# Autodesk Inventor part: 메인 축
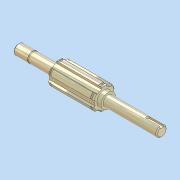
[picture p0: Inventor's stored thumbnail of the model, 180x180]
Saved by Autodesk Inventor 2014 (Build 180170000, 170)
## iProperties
Created: 2012-05
Part Number: 메인 축
Document SubType Name: 모델링
Designer: SeoGD™
Mass: 168.566 g
Surface Area: 72.5104 cm^2
Volume: 21.4461 cm^3
Density: 7.86 g/cm^3
Material: 강철, 연강
Appearance: 강철
변환 표준: STEP AP214IS
파일 이름: C:\Users\SeoGD\Desktop\?쒗뿕\硫붿씤 異?.stp
전처리기: Build: 253, Release: 2010 SP1 - Date: Wed 07/29/2009
전송 단위: 밀리미터
불확실성: 0.01
Author: SeoGD™
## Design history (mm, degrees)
sketch "스케치1"
  geometry: L1 (-69.5, 0)-(69.5, 0); L2 (69.5, 0)-(69.5, 5); L3 (69.5, 5)-(55.5, 5); L4 (55.5, 5)-(55.5, 4.8); L5 (55.5, 4.8)-(54.35, 4.8); L6 (54.35, 4.8)-(54.35, 5); L7 (54.35, 5)-(30.5, 5); L8 (30.5, 5)-(30.5, 9); L9 (30.5, 9)-(-13.5, 9); L10 (-13.5, 9)-(-13.5, 7); L11 (-13.5, 7)-(-17.5, 7); L12 (-17.5, 7)-(-17.5, 5); L13 (-17.5, 5)-(-69.5, 5); L14 (-69.5, 5)-(-69.5, 0); 2 further points
  constraints: 28 end point, 9 parallel, 4 collinear, 2 perpendicular, 1 coincident, 1 horizontal, 1 midpoint
  dimensions: "d2" = 1.15 distance between parallel lines of L6 L4; "d3" = 10 diameter of L3 L1; "d4" = 9.6 diameter of L5 L1; "d6" = 44 distance between parallel lines of L10 L8; "d7" = 4 distance between parallel lines of L12 L10; "d8" = 14 diameter of L11 L1; "d9" = 18 diameter of L9 L1; "d33" = 52 distance from line of L12.end L14; "d37" = 39 distance between parallel lines of L8 L2; "d38" = 14 distance between parallel lines of L2 L4
revolve "회전1" sketch "스케치1" stored, may be unused: angle "d10" = 90 deg
sketch "스케치2"
  geometry: L1 (2.5, 10.712)-(2.5, 8.646); L2 (-2.5, 10.712)-(-2.5, 8.646); A1 r 9 centre (0, 0) between (2.5, 8.646) and (-2.5, 8.646) reference; A2 r 11 centre (0, 0) between (2.5, 10.712) and (-2.5, 10.712); 1 further point
  constraints: 4 end point, 4 point on circle, 2 parallel, 1 centre point, 1 coincident, 1 vertical
  dimensions: "d11" = 22 diameter of A2; "d12" = 5 distance between parallel lines of L1 L2
extrude "돌출1" join sketch "스케치2" stored distance "d13" = 10; taper "d14" = 0 deg
chamfer "모따기1" distance "d15" = 1; stored, may be unused: second distance "d16" = 2, angle "d17" = 45 deg
node "작업 평면1"
node "작업 평면2"
sketch "스케치3"
  geometry: L1 (2.5, 10.712)-(2.5, 10.198); L2 (-2.5, 10.712)-(-2.5, 10.198); A1 r 11 centre (0, 0) between (2.5, 10.712) and (-2.5, 10.712) reference; A2 r 10.5 centre (0, 0) between (2.5, 10.198) and (-2.5, 10.198); 1 further point
  constraints: 4 end point, 2 point on circle, 1 centre point, 1 coincident, 1 parallel, 1 vertical
  dimensions: "d19" = 21 diameter of A2
extrude "돌출2" cut sketch "스케치3" distance "d20" = 1.35; taper "d21" = 0 deg
node "작업 평면3"
sketch "스케치4"
  geometry: L1 (-26, -5)-(-26, 5) reference; L2 (-26, 1.5)-(-12.5, 1.5); L3 (-12.5, -1.5)-(-26, -1.5); A1 r 1.5 centre (-12.5, 0) between (-12.5, -1.5) and (-12.5, 1.5); 2 further points
  constraints: 4 end point, 2 perpendicular, 2 point on circle, 2 point on line, 2 tangent, 1 centre point, 1 horizontal alignment, 1 midpoint
  dimensions: "d25" = 3 distance between parallel lines of L3 L2; "d26" = 15 dimension on A1 L1
extrude "돌출3" cut sketch "스케치4" distance "d27" = 1.8; taper "d28" = 0 deg
chamfer "모따기2" distance "d29" = 1; stored, may be unused: second distance "d30" = 2, angle "d31" = 45 deg
node "솔리드1"
node "솔리드 본체"
node "곡면 본체"
mirror "대칭1"
pattern_circular "원형 패턴1" dims "d23" = 360 deg
node "솔리드2"
other parameters: "d18" = -1.65
